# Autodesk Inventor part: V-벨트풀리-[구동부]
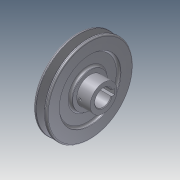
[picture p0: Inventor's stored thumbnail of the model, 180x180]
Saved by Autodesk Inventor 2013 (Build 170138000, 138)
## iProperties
Company: 한국ATC센터
Created: 2014-10
Part Number: V-벨트풀리-[구동부]
Document SubType Name: Modeling
Designer: 한국ATC센터
Density: 7.86 g/cm^3
Material: 강철, 연강
Mass: 1515.01 g
Surface Area: 468.111 cm^2
Volume: 192.75 cm^3
Author: KYOUNG IL JANG
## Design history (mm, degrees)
sketch "스케치1"
  geometry: L1 (-20, 0)-(20, 0); L2 (-20, 0)-(-20, 26); L3 (-20, 26)-(-16, 26); L4 (-16, 26)-(-16, 46); L5 (-16, 46)-(-20, 46); L6 (-20, 46)-(-20, 64.5); L7 (-20, 64.5)-(-16.062, 64.5); L8 (-16.062, 64.5)-(-12.001, 52); L9 (-12.001, 52)-(-7.999, 52); L10 (-7.999, 52)-(-3.938, 64.5); L11 (-3.938, 64.5)-(0, 64.5); L12 (0, 64.5)-(0, 46); L13 (0, 46)-(-4, 46); L14 (-4, 46)-(-4, 26); L15 (-4, 26)-(0, 26); L16 (0, 26)-(0, 20); L17 (0, 20)-(20, 20); L18 (20, 20)-(20, 0); L19 (-14.6, 60)-(-5.4, 60); 2 further points
  constraints: 38 end point, 11 parallel, 7 collinear, 3 equal length, 3 perpendicular, 2 point on line, 1 coincident, 1 horizontal, 1 midpoint
  dimensions: "d0" = 40 distance of L1.start L1.end; "d1" = 4.5 distance between parallel lines of L7 L19; "d2" = 8 distance between parallel lines of L9 L19; "d3" = 9.2 distance of L19.start L19.end; "d4" = 36 deg angle of L10 L8; "d5" = 20 distance between parallel lines of L12 L6; "d6" = 120 diameter of L19 L1; "d7" = 4 distance of L2.end L3.end; "d8" = 52 diameter of L3 L1; "d9" = 92 diameter of L5 L1; "d10" = 40 diameter of L17 L1
revolve "회전1" sketch "스케치1" stored, may be unused: angle "d11" = 90 deg
sketch "스케치2"
  geometry: L1 (-4, 11.843)-(-4, 16.5); L2 (-4, 16.5)-(4, 16.5); L3 (4, 16.5)-(4, 11.843); A1 r 12.5 centre (0, 0) between (-4, 11.843) and (4, 11.843); 1 further point
  constraints: 6 end point, 2 parallel, 2 point on circle, 1 centre point, 1 coincident, 1 horizontal, 1 vertical
  dimensions: "d12" = 25 diameter of A1; "d13" = 8 distance of L1.end L2.end; "d14" = 29 dimension on A1 L2
extrude "돌출1" cut sketch "스케치2" stored distance "d15" = 10; taper "d16" = 0 deg
chamfer "모따기1" distance "d17" = 1; stored, may be unused: second distance "d18" = 2, angle "d19" = 45 deg
node "작업 평면1"
sketch "스케치3"
  geometry: L1 (10, -20)-(10, 20) reference; 3 further points
  constraints: 1 horizontal alignment, 1 midpoint
  dimensions: "d20" = 15 distance from line of L1 point (-5, 0)
hole "구멍1" sketch "스케치3" at (-5, 0) diameter "d21" = 4.459; stored, may be unused: countersink angle "d25" = 90 deg, drill point angle "d27" = 118 deg; dims "d22" = 6, "d23" = 4, "d24" = 2, "d26" = 8
fillet "모깎기1" dims "d28" = 3, "d29" = 2, "d30" = 0.5, "d31" = 1
node "솔리드1"
